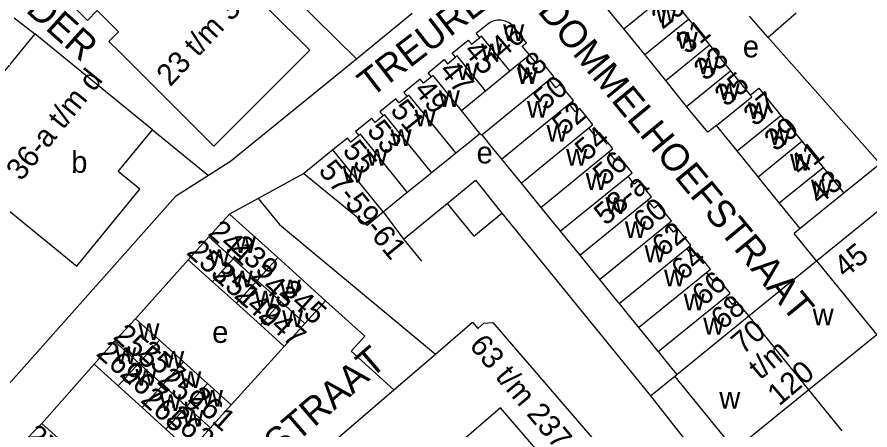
# Model space of a CAD drawing. Extents: x 161775 to 163181, y 382878 to 383925.
# Drawn here: x 162089.5 to 162245.9, y 383208.3 to 383284.1 of the extents above; entities that cross this region are included whole.
import ezdxf

# ---------------------------------------------------------------- set-up
doc = ezdxf.new("R2010")
doc.units = 0
for name, color, linetype in [('BLT_Basislijn', 7, 'Continuous'), ('BLT_Bebouwing', 7, 'Continuous'), ('BLT_Centroide', 7, 'Continuous'), ('BLT_Huisnummer', 7, 'Continuous'), ('BLT_Huisnummer_ tussenligend', 7, 'Continuous'), ('BLT_Huisnummer_reeks', 7, 'Continuous'), ('BLT_Onderdoorgang_en_onderverdeling', 7, 'Continuous'), ('BLT_Onderverdeling_panden', 7, 'Continuous'), ('BLT_Straatnaam', 7, 'Continuous')]:
    doc.layers.add(name, color=color, linetype=linetype)

msp = doc.modelspace()

# ---------------------------------------------------------------- linework, layer by layer
at = {"layer": 'BLT_Basislijn'}
for p, q in [((162119.27, 383308.6), (162151.77, 383276.48)), ((162088.99, 383283.99), (162092.82, 383281.08)), ((162151.77, 383276.48), (162162.02, 383284.83)), ((162128.38, 383257.42), (162151.77, 383276.48)), ((162114.38, 383263.45), (162124.64, 383255.04)), ((162128.38, 383257.42), (162124.64, 383255.04)), ((162124.64, 383255.04), (162118.59, 383251.19)), ((162142.13, 383255.42), (162133.74, 383250.84)), ((162118.59, 383251.19), (162072.53, 383199.31)), ((162133.74, 383250.84), (162128.52, 383247.98)), ((162156.7, 383248.38), (162160.4, 383243.38)), ((162233.15, 383245.31), (162232.06, 383244.42)), ((162160.4, 383243.38), (162163.73, 383239.3)), ((162236.17, 383239.36), (162232.06, 383244.42)), ((162120.93, 383239.57), (162111.27, 383228.77)), ((162128.84, 383212.93), (162138.54, 383223.69)), ((162103.69, 383220.4), (162094.09, 383209.53)), ((162240.84, 383208.2), (162234.74, 383215.7)), ((162205.68, 383214.6), (162216.44, 383200.94))]:
    msp.add_line(p, q, dxfattribs=at)
for points in [[(162227.26, 383280.38), (162247.8, 383257.21), (162241.18, 383251.81)], [(162168.42, 383249.94), (162173.6, 383254.17), (162178.47, 383248.16)], [(162133.74, 383250.84), (162137.65, 383246.04), (162166.3, 383222.28)], [(162160.4, 383243.38), (162168.42, 383249.94)], [(162168.42, 383249.94), (162173.3, 383243.91), (162178.47, 383248.16)], [(162178.47, 383248.16), (162205.68, 383214.6)], [(162146.12, 383232.06), (162153.32, 383225.56), (162150.82, 383222.8), (162158.66, 383215.71)], [(162205.68, 383214.6), (162210.16, 383218.23)]]:
    msp.add_lwpolyline(points, dxfattribs=at)
at = {"layer": 'BLT_Bebouwing'}
for p, q in [((162208.83, 383288.49), (162212.67, 383283.77)), ((162200.8, 383281.97), (162196.86, 383286.82)), ((162212.67, 383283.77), (162216.53, 383279.02)), ((162227.26, 383280.38), (162223.85, 383284.29)), ((162114.38, 383263.45), (162092.82, 383281.08)), ((162204.64, 383277.24), (162200.8, 383281.97)), ((162216.53, 383279.02), (162220.38, 383274.28)), ((162208.5, 383272.5), (162204.64, 383277.24)), ((162220.38, 383274.28), (162224.01, 383269.81)), ((162212.32, 383267.74), (162208.5, 383272.5)), ((162224.01, 383269.81), (162225.57, 383271.08)), ((162225.57, 383271.08), (162229.63, 383266.07)), ((162216.22, 383262.98), (162212.32, 383267.74)), ((162229.63, 383266.07), (162233.47, 383261.33)), ((162217.8, 383264.26), (162216.22, 383262.98)), ((162221.6, 383259.57), (162217.8, 383264.26)), ((162174.77, 383262.5), (162176.68, 383260.16)), ((162169.98, 383259.19), (162172.31, 383261.07)), ((162233.47, 383261.33), (162237.34, 383256.55)), ((162225.44, 383254.83), (162221.6, 383259.57)), ((162165.53, 383255.59), (162167.9, 383257.5)), ((162178.4, 383258.07), (162180.28, 383255.73)), ((162237.34, 383256.55), (162241.18, 383251.81)), ((162229.31, 383250.05), (162225.44, 383254.83)), ((162181.98, 383253.62), (162185.59, 383249.19)), ((162241.18, 383251.81), (162233.15, 383245.31)), ((162156.69, 383248.38), (162159.07, 383250.31)), ((162233.15, 383245.31), (162229.31, 383250.05)), ((162128.52, 383247.98), (162124.74, 383243.79)), ((162137.35, 383240), (162128.52, 383247.98)), ((162185.59, 383249.19), (162187.48, 383246.87)), ((162124.74, 383243.79), (162120.93, 383239.57)), ((162146.12, 383232.06), (162137.35, 383240)), ((162120.93, 383239.57), (162125.39, 383235.55)), ((162125.39, 383235.55), (162129.77, 383231.6)), ((162142.33, 383227.87), (162146.12, 383232.06)), ((162129.77, 383231.6), (162134.16, 383227.64)), ((162199.93, 383231.55), (162201.86, 383229.19)), ((162111.27, 383228.77), (162107.4, 383224.62)), ((162111.27, 383228.77), (162115.67, 383224.8)), ((162134.16, 383227.64), (162138.54, 383223.69)), ((162138.54, 383223.69), (162142.33, 383227.87)), ((162203.52, 383227.14), (162205.44, 383224.77)), ((162107.4, 383224.62), (162103.69, 383220.4)), ((162115.67, 383224.8), (162120.07, 383220.84)), ((162207.13, 383222.72), (162209.01, 383220.38)), ((162158.66, 383215.71), (162166.3, 383222.28)), ((162103.69, 383220.4), (162108.07, 383216.43)), ((162120.07, 383220.84), (162124.46, 383216.87)), ((162108.07, 383216.43), (162112.46, 383212.45)), ((162128.84, 383212.93), (162124.46, 383216.87)), ((162112.46, 383212.45), (162116.84, 383208.47)), ((162125.03, 383208.71), (162128.84, 383212.93)), ((162090.1, 383205.49), (162094.09, 383209.53)), ((162094.09, 383209.53), (162098.38, 383205.66)), ((162121.22, 383204.49), (162125.03, 383208.71)), ((162116.84, 383208.47), (162121.22, 383204.49))]:
    msp.add_line(p, q, dxfattribs=at)
for points in [[(162113.79, 383294.87), (162095.85, 383312.66), (162084.57, 383301.31), (162102.48, 383283.52), (162104.26, 383285.33)], [(162104.26, 383285.33), (162108.15, 383281.44), (162106.4, 383279.68), (162108.41, 383277.67), (162125.62, 383260.44), (162143.21, 383278.05), (162120.07, 383301.15), (162113.79, 383294.87)], [(162232.4, 383284.87), (162227.26, 383280.38)], [(162180.56, 383282.38), (162180.25, 383282.71), (162179.97, 383282.93), (162179.65, 383283.14), (162179.37, 383283.28), (162179.03, 383283.41), (162178.63, 383283.52), (162178.28, 383283.57), (162177.99, 383283.58), (162177.58, 383283.55), (162177.28, 383283.5), (162177.03, 383283.43), (162176.71, 383283.32), (162176.41, 383283.18), (162176.1, 383282.99), (162175.86, 383282.81), (162173.75, 383281.09), (162174.36, 383280.35)], [(162182.97, 383279.39), (162180.56, 383282.38)], [(162092.82, 383281.08), (162074.98, 383259.26), (162100.5, 383238.38), (162112.07, 383252.52), (162108.1, 383255.76), (162114.38, 383263.45)], [(162169.95, 383276.76), (162169.33, 383277.5), (162172.29, 383279.91)], [(162172.29, 383279.91), (162172.9, 383279.16), (162174.36, 383280.35)], [(162183.5, 383277.19), (162182.2, 383278.77), (162182.97, 383279.39)], [(162165.53, 383273.17), (162164.91, 383273.91), (162167.88, 383276.32)], [(162167.88, 383276.32), (162168.48, 383275.57), (162169.95, 383276.76)], [(162185.55, 383276.22), (162184.79, 383275.61), (162183.5, 383277.19)], [(162187.96, 383273.25), (162185.55, 383276.22)], [(162163.46, 383272.72), (162160.49, 383270.31), (162161.1, 383269.57)], [(162165.53, 383273.17), (162164.07, 383271.98), (162163.46, 383272.72)], [(162187.18, 383272.65), (162187.96, 383273.25)], [(162189.13, 383271.78), (162188.37, 383271.16), (162187.18, 383272.65)], [(162191.56, 383268.82), (162189.13, 383271.78)], [(162161.1, 383269.57), (162159.64, 383268.38), (162159.03, 383269.13)], [(162159.03, 383269.13), (162156.06, 383266.72), (162156.66, 383265.99)], [(162190.8, 383268.2), (162191.56, 383268.82)], [(162192.72, 383267.36), (162191.97, 383266.74), (162190.8, 383268.2)], [(162195.15, 383264.4), (162192.72, 383267.36)], [(162154.59, 383265.54), (162151.63, 383263.12)], [(162156.66, 383265.99), (162155.19, 383264.8), (162154.59, 383265.54)], [(162194.39, 383263.78), (162195.15, 383264.4)], [(162196.34, 383262.94), (162195.58, 383262.32), (162194.39, 383263.78)], [(162150.17, 383261.93), (162147.47, 383259.75)], [(162152.24, 383262.38), (162150.77, 383261.19), (162150.17, 383261.93)], [(162151.63, 383263.12), (162152.24, 383262.38)], [(162172.31, 383261.07), (162174.44, 383262.79)], [(162174.44, 383262.79), (162174.71, 383262.46), (162174.77, 383262.5)], [(162198.79, 383260), (162196.34, 383262.94)], [(162176.68, 383260.16), (162178.16, 383258.34), (162178.4, 383258.07)], [(162147.47, 383259.75), (162142.13, 383255.42)], [(162167.9, 383257.5), (162169.98, 383259.19)], [(162198.04, 383259.37), (162198.79, 383260)], [(162199.95, 383258.52), (162199.19, 383257.91), (162198.04, 383259.37)], [(162202.34, 383255.54), (162199.95, 383258.52)], [(162161.11, 383251.99), (162165.29, 383255.37), (162165.53, 383255.59)], [(162180.28, 383255.73), (162181.98, 383253.62)], [(162201.58, 383254.93), (162202.34, 383255.54)], [(162142.13, 383255.42), (162153.73, 383245.91), (162156.7, 383248.38)], [(162203.49, 383254.08), (162202.73, 383253.46), (162201.58, 383254.93)], [(162205.9, 383251.13), (162203.49, 383254.08)], [(162159.07, 383250.31), (162161.11, 383251.99)], [(162205.15, 383250.51), (162205.9, 383251.13)], [(162207.12, 383249.65), (162206.36, 383249.03), (162205.15, 383250.51)], [(162209.53, 383246.7), (162207.12, 383249.65)], [(162236.17, 383239.36), (162249.73, 383250.39)], [(162187.48, 383246.87), (162188.95, 383245.07), (162189.16, 383244.82)], [(162208.77, 383246.08), (162209.53, 383246.7)], [(162189.16, 383244.82), (162192.77, 383240.42)], [(162210.7, 383245.24), (162209.94, 383244.63), (162208.77, 383246.08)], [(162213.12, 383242.27), (162210.7, 383245.24)], [(162212.36, 383241.66), (162213.12, 383242.27)], [(162214.3, 383240.82), (162213.54, 383240.2), (162212.36, 383241.66)], [(162192.77, 383240.42), (162196.34, 383235.98)], [(162216.71, 383237.85), (162214.3, 383240.82)], [(162223.72, 383229.27), (162236.17, 383239.36)], [(162215.95, 383237.23), (162216.71, 383237.85)], [(162217.91, 383236.39), (162217.15, 383235.77), (162215.95, 383237.23)], [(162196.34, 383235.98), (162199.71, 383231.81), (162199.93, 383231.55)], [(162220.32, 383233.44), (162217.91, 383236.39)], [(162219.56, 383232.82), (162220.32, 383233.44)], [(162221.49, 383231.99), (162220.73, 383231.37), (162219.56, 383232.82)], [(162223.72, 383229.27), (162221.49, 383231.99)], [(162201.86, 383229.19), (162203.31, 383227.38), (162203.52, 383227.14)], [(162166.3, 383222.28), (162173.07, 383228.1), (162174.03, 383226.97), (162175.16, 383227.93), (162176.8, 383228.04), (162221.04, 383176.6)], [(162247.18, 383225.8), (162234.74, 383215.7)], [(162205.44, 383224.77), (162207.11, 383222.7), (162207.13, 383222.72)], [(162209.01, 383220.38), (162210.51, 383218.53)], [(162210.16, 383218.23), (162210.51, 383218.53)], [(162221.17, 383204.67), (162210.16, 383218.23)], [(162098.24, 383157.17), (162094.99, 383160.95), (162158.66, 383215.71)], [(162234.74, 383215.7), (162221.17, 383204.67)]]:
    msp.add_lwpolyline(points, dxfattribs=at)
at = {"layer": 'BLT_Onderdoorgang_en_onderverdeling'}
for p, q in [((162236.17, 383239.36), (162247.18, 383225.8)), ((162234.74, 383215.7), (162223.72, 383229.27))]:
    msp.add_line(p, q, dxfattribs=at)
at = {"layer": 'BLT_Onderverdeling_panden'}
for p, q in [((162200.8, 383281.97), (162208.83, 383288.49)), ((162204.64, 383277.24), (162212.67, 383283.77)), ((162208.5, 383272.5), (162216.53, 383279.02)), ((162179.89, 383274.24), (162183.5, 383277.19)), ((162175.46, 383270.62), (162179.89, 383274.24)), ((162212.32, 383267.74), (162220.38, 383274.28)), ((162174.77, 383262.5), (162187.18, 383272.65)), ((162171.03, 383267.01), (162175.46, 383270.62)), ((162178.4, 383258.07), (162190.8, 383268.2)), ((162174.44, 383262.79), (162171.03, 383267.01)), ((162221.6, 383259.57), (162229.63, 383266.07)), ((162181.98, 383253.62), (162194.39, 383263.78)), ((162225.44, 383254.83), (162233.47, 383261.33)), ((162156.69, 383248.38), (162147.47, 383259.75)), ((162185.59, 383249.19), (162198.04, 383259.37)), ((162229.31, 383250.05), (162237.34, 383256.55)), ((162189.16, 383244.82), (162201.58, 383254.93)), ((162192.77, 383240.42), (162205.15, 383250.51)), ((162196.34, 383235.98), (162208.77, 383246.08)), ((162124.74, 383243.79), (162129.19, 383239.77)), ((162199.94, 383231.56), (162212.36, 383241.66)), ((162133.57, 383235.8), (162137.35, 383240)), ((162129.19, 383239.77), (162125.39, 383235.55)), ((162129.19, 383239.77), (162133.57, 383235.8)), ((162203.52, 383227.14), (162215.95, 383237.23)), ((162133.57, 383235.8), (162129.77, 383231.6)), ((162133.57, 383235.8), (162137.95, 383231.84)), ((162207.13, 383222.72), (162219.56, 383232.82)), ((162137.95, 383231.84), (162134.16, 383227.64)), ((162137.95, 383231.84), (162142.33, 383227.87)), ((162107.4, 383224.62), (162111.86, 383220.6)), ((162111.86, 383220.6), (162115.67, 383224.8)), ((162108.07, 383216.43), (162111.86, 383220.6)), ((162111.86, 383220.6), (162116.25, 383216.63)), ((162116.25, 383216.63), (162120.07, 383220.84)), ((162116.25, 383216.63), (162112.46, 383212.45)), ((162116.25, 383216.63), (162120.65, 383212.67)), ((162120.65, 383212.67), (162124.46, 383216.87)), ((162116.84, 383208.47), (162120.65, 383212.67)), ((162120.65, 383212.67), (162125.03, 383208.71))]:
    msp.add_line(p, q, dxfattribs=at)
for points in [[(162179.89, 383274.24), (162174.71, 383280.64), (162174.36, 383280.35)], [(162175.46, 383270.62), (162170.27, 383277.03), (162169.95, 383276.76)], [(162171.03, 383267.01), (162165.84, 383273.42), (162165.53, 383273.17)], [(162169.98, 383259.19), (162161.4, 383269.81), (162161.1, 383269.57)], [(162217.8, 383264.26), (162224.27, 383269.5), (162224.01, 383269.81)], [(162165.53, 383255.59), (162156.94, 383266.22), (162156.66, 383265.99)], [(162161.11, 383251.99), (162152.54, 383262.62), (162152.24, 383262.38)], [(162210.51, 383218.53), (162223.72, 383229.27)], [(162208.44, 383177.2), (162178.19, 383212.41), (162112.09, 383155.29), (162140.45, 383122.3), (162139.22, 383117.78)]]:
    msp.add_lwpolyline(points, dxfattribs=at)

# ---------------------------------------------------------------- texts
at = {"layer": 'BLT_Centroide'}
for s, p in [('w', (162206.67, 383283.09)), ('w', (162178.68, 383279.72)), ('w', (162210.52, 383278.34)), ('w', (162174.65, 383276.17)), ('e', (162222.64, 383276.74)), ('w', (162214.36, 383273.62)), ('w', (162170.23, 383272.58)), ('w', (162181.19, 383271.86)), ('w', (162218.2, 383268.88)), ('w', (162166.89, 383267.64)), ('w', (162183.05, 383265.67)), ('w', (162223.6, 383265.41)), ('w', (162162.47, 383264.05)), ('w', (162158.04, 383260.45)), ('w', (162186.65, 383261.27)), ('w', (162227.45, 383260.66)), ('e', (162173.81, 383257.27)), ('b', (162099.48, 383255.54)), ('w', (162153.62, 383256.86)), ('w', (162190.24, 383256.83)), ('w', (162231.29, 383255.94)), ('w', (162149.25, 383253.72)), ('w', (162193.83, 383252.42)), ('w', (162235.13, 383251.19)), ('w', (162197.42, 383247.98)), ('w', (162201.01, 383243.55)), ('w', (162129.49, 383240.81)), ('w', (162124.68, 383238.44)), ('w', (162204.61, 383239.14)), ('w', (162128.91, 383234.52)), ('w', (162208.19, 383234.7)), ('w', (162137.71, 383232.85)), ('w', (162133.13, 383230.84)), ('w', (162211.79, 383230.3)), ('w', (162235.44, 383227.55)), ('w', (162138.15, 383227.23)), ('w', (162215.38, 383225.86)), ('w', (162111.8, 383224.84)), ('e', (162125.33, 383224.32)), ('w', (162107.56, 383220.45)), ('w', (162116.33, 383219.77)), ('w', (162111.26, 383216.47)), ('w', (162119.48, 383216.06)), ('w', (162115.78, 383211.81)), ('w', (162123.45, 383212.63)), ('w', (162218.32, 383212.25)), ('w', (162119.89, 383208.93))]:
    msp.add_text(s, height=4, dxfattribs=at).set_placement(p)
at = {"layer": 'BLT_Huisnummer'}
for s, rotation, p in [('46', 40.6666, (162178.53, 383276.39)), ('31', 39.0628, (162212.41, 383277.14)), ('45', 309.0641, (162171.29, 383277.85)), ('50', 40.6666, (162186.36, 383266.83)), ('35', 39.0628, (162219.52, 383267.52)), ('49', 309.0641, (162162.15, 383270.64)), ('53', 309.0641, (162153.54, 383263.23)), ('39', 39.0628, (162228.63, 383259.3)), ('54', 40.6666, (162194, 383257.55)), ('43', 39.0628, (162236.66, 383249.53)), ('241', 318, (162124.38, 383244.28)), ('62', 40.6666, (162208.1, 383239.94)), ('253', 318, (162120.43, 383240.74)), ('239', 318, (162128.59, 383241.54)), ('251', 318, (162125.22, 383236.41)), ('243', 318, (162132.11, 383236.32)), ('249', 318, (162129.17, 383232.8)), ('245', 318, (162137.41, 383233.41)), ('68', 40.6666, (162218.91, 383226.56)), ('247', 318, (162133.62, 383229.14)), ('255', 318, (162106.99, 383225.26)), ('269', 318, (162103.86, 383222.16)), ('257', 318, (162111.52, 383222.2)), ('267', 318, (162108.21, 383218.36)), ('259', 318, (162115.27, 383217.24)), ('265', 318, (162112.02, 383213.6)), ('261', 318, (162120.68, 383213.82)), ('263', 318, (162116.84, 383210.34)), ('271', 318, (162090.64, 383206.77))]:
    msp.add_text(s, height=4, rotation=rotation, dxfattribs=at).set_placement(p)
at = {"layer": 'BLT_Huisnummer_ tussenligend'}
for s, rotation, p in [('29', 39.0628, (162207.9, 383281.75)), ('48', 40.6666, (162182.59, 383271.29)), ('33', 39.0628, (162215.71, 383272.26)), ('47', 309.0641, (162166.79, 383274.22)), ('37', 39.0628, (162224.81, 383263.92)), ('51', 309.0641, (162157.84, 383266.98)), ('52', 40.6666, (162189.83, 383262.16)), ('55', 309.0641, (162149.06, 383259.55)), ('41', 39.0628, (162233.24, 383254.8)), ('56', 40.6666, (162197.3, 383253)), ('60', 40.6666, (162204.67, 383244.37)), ('64', 40.6666, (162211.66, 383235.6)), ('66', 40.6666, (162215.45, 383230.93))]:
    msp.add_text(s, height=4, rotation=rotation, dxfattribs=at).set_placement(p)
at = {"layer": 'BLT_Huisnummer_reeks'}
for s, rotation, p in [('23 t/m 39', 47.0641, (162117.64, 383271.23)), ('36-a t/m d', 51, (162090.3, 383253.85)), ('57-59-61', 309.0641, (162144.66, 383255.9)), ('58-a', 40.6666, (162197.5, 383245.73)), ('45', 39.063, (162241.39, 383236.1)), ('70', 40.2651, (162222.63, 383222.06)), ('63 t/m 237', 310, (162172.32, 383223.77)), ('t/m', 40.2651, (162225.81, 383217.41)), ('120', 40.2651, (162229.27, 383212.59))]:
    msp.add_text(s, height=4, rotation=rotation, dxfattribs=at).set_placement(p)
at = {"layer": 'BLT_Straatnaam'}
for s, rotation, p in [('TREURENBURGSTRAAT', 37.6265, (162154.49, 383269.26)), ('GASHOUDER', 318.0001, (162069.45, 383304.59)), ('DOMMELHOEFSTRAAT', 309.5461, (162184.87, 383285.16)), ('TREURENBURGSTRAAT', 40.6265, (162098.34, 383169.54))]:
    msp.add_text(s, height=5, rotation=rotation, dxfattribs=at).set_placement(p)

doc.saveas('drawing.dxf')
